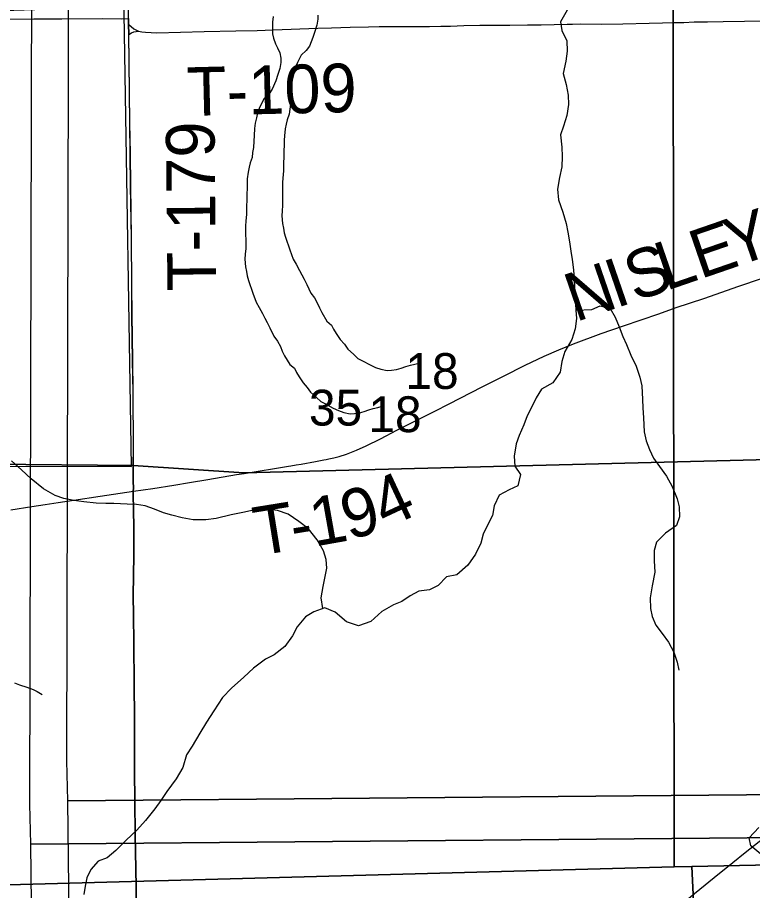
# Model space of a CAD drawing. Extents: x -21.1 to 50.3, y -4.9 to 22.1.
# Drawn here: x 2.72 to 3.578, y 15.856 to 16.876 of the extents above; entities that cross this region are included whole.
import ezdxf

# ---------------------------------------------------------------- set-up
doc = ezdxf.new("R2010")
doc.units = 0
for name, color, linetype in [('GM_X_Corporation', 7, 'Continuous'), ('GM_X_County_Road', 7, 'Continuous'), ('GM_X_Minor_River', 7, 'Continuous'), ('GM_X_Rail_Line_Text', 7, 'Continuous'), ('GM_X_Section', 7, 'Continuous'), ('GM_X_Section_Text', 7, 'Continuous'), ('GM_X_State_Route', 7, 'Continuous'), ('GM_X_Township_Road', 7, 'Continuous'), ('GM_X_Township_Road_Text', 7, 'Continuous'), ('SH_Cut_Line', 7, 'Continuous')]:
    doc.layers.add(name, color=color, linetype=linetype)

msp = doc.modelspace()

# ---------------------------------------------------------------- linework, layer by layer
at = {"layer": 'GM_X_Corporation'}
msp.add_lwpolyline([(2.1, 17.3693), (2.1, 16.3531), (2.8527, 16.3513), (2.8363, 17.363), (2.8365, 17.3865)], close=True, dxfattribs=at)
at = {"layer": 'GM_X_County_Road'}
for p, q in [((2.8491, 16.8748), (2.8493, 16.8682)), ((2.8493, 16.8682), (2.8496, 16.8562))]:
    msp.add_line(p, q, dxfattribs=at)
for points in [[(2.3484, 16.8666), (2.3505, 16.8667), (2.4002, 16.8675), (2.4654, 16.8688), (2.5213, 16.8703), (2.5555, 16.8712), (2.5834, 16.872), (2.6299, 16.8728), (2.6579, 16.8733), (2.6827, 16.8738), (2.7076, 16.8743), (2.7386, 16.8746), (2.7714, 16.8746), (2.8194, 16.8748), (2.8411, 16.8746), (2.8491, 16.8748)], [(2.8493, 16.8682), (2.85, 16.8675), (2.8525, 16.8654), (2.8554, 16.863), (2.858, 16.8615), (2.8601, 16.8606), (2.8608, 16.8603)], [(2.8608, 16.8603), (2.8647, 16.8593), (2.869, 16.8588), (2.8823, 16.8583), (2.9377, 16.8596), (2.9748, 16.8605), (2.9997, 16.861), (3.0182, 16.8615), (3.0705, 16.8635), (3.0863, 16.864), (3.1081, 16.8648), (3.1298, 16.8653), (3.1422, 16.8655), (3.1698, 16.8656), (3.1884, 16.8657), (3.201, 16.8657), (3.2144, 16.8659), (3.2257, 16.866), (3.2412, 16.8667), (3.2597, 16.8671), (3.2785, 16.867), (3.2949, 16.8671), (3.3156, 16.8674), (3.3314, 16.8674), (3.3619, 16.8682), (3.368, 16.8682), (3.3775, 16.8685), (3.402, 16.8684), (3.4268, 16.8687), (3.4577, 16.8693), (3.4731, 16.8698), (3.4854, 16.8701), (3.498, 16.8703), (3.5103, 16.8709), (3.5257, 16.8711), (3.5443, 16.8714), (3.5692, 16.8717), (3.594, 16.8722)], [(2.8496, 16.8562), (2.8529, 16.8581), (2.8556, 16.8593), (2.8608, 16.8603)], [(2.8551, 16.3226), (2.8776, 16.3259), (2.9021, 16.3297), (2.9205, 16.3328), (2.9419, 16.3364), (2.9756, 16.342), (2.9843, 16.3434)], [(2.7117, 16.301), (2.7363, 16.3048), (2.7517, 16.307), (2.767, 16.3094), (2.7854, 16.3121), (2.8162, 16.3167), (2.8551, 16.3226)]]:
    msp.add_lwpolyline(points, dxfattribs=at)
at = {"layer": 'GM_X_Minor_River'}
for points in [[(3.3619, 16.8848), (3.3542, 16.8712), (3.3557, 16.8609), (3.3613, 16.8487), (3.362, 16.8366), (3.3604, 16.8252), (3.3573, 16.8105), (3.3606, 16.7979), (3.3632, 16.7854), (3.3635, 16.7744), (3.3615, 16.7615), (3.3576, 16.749), (3.3541, 16.7388), (3.3556, 16.7247), (3.3562, 16.7137), (3.3558, 16.7016), (3.3527, 16.6891), (3.3507, 16.6754), (3.3517, 16.6629), (3.3566, 16.6488), (3.3607, 16.6355), (3.3625, 16.6253), (3.3647, 16.6139), (3.3661, 16.6032), (3.3676, 16.5934), (3.3694, 16.5812), (3.3701, 16.5691), (3.3708, 16.5554), (3.3721, 16.5342), (3.3728, 16.5243), (3.3712, 16.5122), (3.3674, 16.5), (3.3593, 16.486), (3.3558, 16.4743), (3.3535, 16.4618), (3.345, 16.4493), (3.3317, 16.4418), (3.3256, 16.4316), (3.3206, 16.421), (3.3152, 16.4108), (3.3113, 16.4002), (3.3059, 16.3877), (3.3024, 16.3779), (3.3001, 16.3635), (3.3007, 16.3517), (3.3075, 16.3422), (3.3044, 16.3289), (3.2941, 16.3241), (3.2823, 16.3181), (3.2765, 16.3056), (3.2746, 16.2942), (3.2696, 16.2844), (3.2638, 16.2723), (3.2611, 16.262), (3.2549, 16.2492), (3.2457, 16.236), (3.2331, 16.225), (3.221, 16.2225), (3.211, 16.2126), (3.2011, 16.2074), (3.1886, 16.206), (3.1783, 16.2003), (3.1688, 16.1939), (3.1589, 16.1898), (3.1452, 16.1819), (3.1326, 16.1703), (3.1181, 16.1654), (3.1041, 16.1701), (3.0909, 16.1811), (3.0788, 16.1865), (3.0659, 16.1817), (3.056, 16.176), (3.0464, 16.164), (3.041, 16.1537)], [(3.0185, 16.8774), (3.0174, 16.8706), (3.0175, 16.8569), (3.0187, 16.8519), (3.021, 16.8455), (3.0233, 16.8406), (3.026, 16.8349), (3.0272, 16.8284), (3.0273, 16.8235), (3.0262, 16.8166), (3.0236, 16.8094), (3.0214, 16.8021), (3.0173, 16.7922), (3.0135, 16.7869), (3.0079, 16.7815), (3.0034, 16.7731), (3.0004, 16.7662), (2.9989, 16.759), (2.9971, 16.7525), (2.9964, 16.7464), (2.9961, 16.7381), (2.9957, 16.7316), (2.9954, 16.724), (2.9943, 16.7183), (2.9936, 16.7126), (2.9914, 16.7061), (2.9903, 16.7011), (2.9892, 16.6954), (2.9881, 16.6874), (2.9878, 16.6821), (2.9878, 16.676), (2.9875, 16.6703), (2.9876, 16.6627), (2.9873, 16.6555), (2.987, 16.6463), (2.9863, 16.638), (2.9859, 16.6326), (2.9862, 16.606), (2.9854, 16.5995), (2.9851, 16.5938), (2.986, 16.5847), (2.9871, 16.5794), (2.9879, 16.5741), (2.9895, 16.5688), (2.9946, 16.554), (2.9985, 16.5434), (3.0019, 16.5373), (3.0058, 16.5301), (3.0085, 16.5248), (3.0112, 16.5199), (3.0143, 16.5135), (3.019, 16.5036), (3.0232, 16.4979), (3.0267, 16.4915), (3.029, 16.4862), (3.0317, 16.4809), (3.0379, 16.4707), (3.0432, 16.4662), (3.0456, 16.4612), (3.0486, 16.4563), (3.0533, 16.4491), (3.0582, 16.4439), (3.0621, 16.4382), (3.069, 16.4322), (3.074, 16.4273), (3.0793, 16.4246), (3.0885, 16.4198), (3.0946, 16.4168), (3.1007, 16.4145), (3.1083, 16.4131), (3.1133, 16.4135), (3.1193, 16.4143), (3.1246, 16.4159), (3.13, 16.4178), (3.1353, 16.4194), (3.1406, 16.4206), (3.1455, 16.4218)], [(3.0705, 16.8789), (3.0706, 16.874), (3.0695, 16.8671), (3.0669, 16.8599), (3.0647, 16.8527), (3.0606, 16.8427), (3.0568, 16.8374), (3.0512, 16.832), (3.0467, 16.8236), (3.0437, 16.8167), (3.0422, 16.8095), (3.0404, 16.803), (3.0397, 16.7969), (3.0394, 16.7886), (3.039, 16.7821), (3.0387, 16.7745), (3.0376, 16.7688), (3.0369, 16.7631), (3.0347, 16.7566), (3.0336, 16.7516), (3.0325, 16.7459), (3.0314, 16.7379), (3.0311, 16.7326), (3.0311, 16.7265), (3.0308, 16.7208), (3.0309, 16.7132), (3.0305, 16.706), (3.0302, 16.6968), (3.0296, 16.6885), (3.0292, 16.6832), (3.0294, 16.6565), (3.0287, 16.6501), (3.0284, 16.6444), (3.0292, 16.6352), (3.0304, 16.6299), (3.0312, 16.6246), (3.0328, 16.6193), (3.0379, 16.6045), (3.0418, 16.5939), (3.0452, 16.5878), (3.0491, 16.5806), (3.0518, 16.5753), (3.0545, 16.5704), (3.0576, 16.564), (3.0622, 16.5541), (3.0665, 16.5485), (3.07, 16.542), (3.0723, 16.5367), (3.075, 16.5314), (3.0812, 16.5212), (3.0865, 16.5167), (3.0888, 16.5118), (3.0919, 16.5068), (3.0966, 16.4997), (3.1015, 16.4944), (3.1054, 16.4887), (3.1123, 16.4827), (3.1173, 16.4778), (3.1226, 16.4751), (3.1318, 16.4703), (3.1379, 16.4673), (3.144, 16.4651), (3.1516, 16.4636), (3.1565, 16.464), (3.1626, 16.4648), (3.1679, 16.4664), (3.1732, 16.4683), (3.1786, 16.4699), (3.1839, 16.4711), (3.1888, 16.4723)], [(3.3722, 16.534), (3.3907, 16.5348), (3.4003, 16.5393), (3.412, 16.5362), (3.418, 16.5259), (3.4225, 16.5145), (3.427, 16.5035), (3.4311, 16.494), (3.4363, 16.4814), (3.4423, 16.4688), (3.4468, 16.4559), (3.449, 16.4457), (3.45, 16.4297), (3.4503, 16.4202), (3.451, 16.4085), (3.452, 16.3921), (3.4542, 16.3815), (3.458, 16.3712), (3.4628, 16.3613), (3.4696, 16.3514), (3.4779, 16.34), (3.4846, 16.3282), (3.4902, 16.3138), (3.4928, 16.3043), (3.4931, 16.2925), (3.4896, 16.2826), (3.4767, 16.2736), (3.4664, 16.2631), (3.4636, 16.2532), (3.4636, 16.2411), (3.4642, 16.2282), (3.4611, 16.2119), (3.4587, 16.1982), (3.4594, 16.1857), (3.4612, 16.1762), (3.4654, 16.1659), (3.4729, 16.1564), (3.4804, 16.1461), (3.4864, 16.1347), (3.4905, 16.1229), (3.4923, 16.1134)], [(3.0765, 16.1857), (3.0743, 16.1979), (3.0767, 16.2112), (3.0787, 16.221), (3.081, 16.2328), (3.0803, 16.243), (3.077, 16.2529), (3.0698, 16.2659), (3.0597, 16.2785), (3.0484, 16.2873), (3.0359, 16.2957), (3.0234, 16.2999), (3.0086, 16.3019), (2.9953, 16.3005), (2.9828, 16.2979), (2.9691, 16.2949), (2.9516, 16.2909), (2.9395, 16.2891), (2.9247, 16.2891), (2.9118, 16.2915), (2.9, 16.2946), (2.8902, 16.2973), (2.8796, 16.3016), (2.8686, 16.3054), (2.8588, 16.307), (2.8478, 16.3075), (2.8322, 16.3083), (2.8227, 16.3084), (2.8113, 16.3088), (2.7969, 16.31), (2.7852, 16.3116), (2.7738, 16.314), (2.7636, 16.3175), (2.75, 16.3255), (2.7356, 16.337), (2.7243, 16.3477), (2.7126, 16.358)], [(3.041, 16.1537), (3.0318, 16.1413), (3.0196, 16.1315), (3.0094, 16.1262), (2.9952, 16.1157), (2.9842, 16.1055), (2.9697, 16.0923), (2.959, 16.0814), (2.949, 16.0659), (2.9406, 16.0527), (2.9325, 16.0398), (2.9237, 16.0247), (2.9172, 16.0145), (2.9129, 15.9997), (2.9048, 15.9865), (2.8941, 15.9718), (2.8872, 15.9612), (2.8799, 15.9514), (2.8692, 15.9378), (2.8589, 15.9265), (2.8467, 15.9148), (2.8345, 15.9027), (2.8242, 15.8944), (2.8139, 15.8903), (2.8051, 15.8805), (2.8005, 15.8707), (2.7985, 15.8612), (2.7969, 15.8513)], [(2.7159, 16.0988), (2.722, 16.0962), (2.7304, 16.0936), (2.7377, 16.091), (2.7426, 16.0884), (2.7483, 16.085)], [(3.588, 15.8986), (3.5764, 15.9083), (3.5746, 15.9178), (3.5859, 15.9298)]]:
    msp.add_lwpolyline(points, dxfattribs=at)
at = {"layer": 'GM_X_Rail_Line_Text'}
for points in [[(2.8489, 16.8892), (2.8489, 16.8754), (2.8491, 16.8687), (2.8494, 16.8567), (2.8498, 16.8245), (2.8506, 16.7532), (2.8511, 16.7173), (2.8516, 16.6794), (2.8524, 16.6191), (2.8528, 16.563), (2.8531, 16.5288), (2.8538, 16.4761), (2.8544, 16.4387), (2.8548, 16.3733), (2.8547, 16.3527), (2.9841, 16.3439), (3.8594, 16.3662)], [(3.8594, 16.3662), (2.9841, 16.3439), (2.8547, 16.3527), (2.8548, 16.3349), (2.855, 16.3256), (2.8549, 16.3231), (2.8548, 16.3167), (2.8552, 16.303), (2.8554, 16.278), (2.8554, 16.2486), (2.8551, 16.2233), (2.8549, 16.2016), (2.8552, 16.1768), (2.8554, 16.1457), (2.8559, 16.096), (2.8561, 16.0588), (2.8563, 16.0308), (2.8564, 16.006), (2.8567, 15.9502), (2.857, 15.9316), (2.8572, 15.9223), (2.8581, 15.8603), (2.8583, 15.8417)], [(2.8583, 15.8417), (2.8581, 15.8603), (2.8572, 15.9223), (2.857, 15.9316), (2.8567, 15.9502), (2.8564, 16.006), (2.8563, 16.0308), (2.8561, 16.0588), (2.8559, 16.096), (2.8554, 16.1457), (2.8552, 16.1768), (2.8549, 16.2016), (2.8551, 16.2233), (2.8554, 16.2486), (2.8554, 16.278), (2.8552, 16.303), (2.8548, 16.3167), (2.8549, 16.3231), (2.855, 16.3256), (2.8548, 16.3349), (2.8547, 16.3527), (2.3532, 16.3572), (2.1, 16.3492), (2.1, 14.1)]]:
    msp.add_lwpolyline(points, dxfattribs=at)
at = {"layer": 'GM_X_Section'}
for points in [[(3.8217, 16.9904), (3.8359, 15.9702), (2.7784, 15.9607), (2.7773, 16.0074), (2.7797, 16.9773)], [(3.7784, 16.9399), (3.7926, 15.9197), (2.7351, 15.9102), (2.734, 15.9568), (2.7365, 16.9268)], [(3.4856, 16.8942), (3.4867, 15.8836), (2.5208, 15.8578), (2.478, 15.8578), (2.4791, 16.8774), (2.9755, 16.8927)], [(4.4944, 16.9022), (4.4951, 15.9048), (3.5076, 15.884), (3.4867, 15.8836), (3.4856, 16.8942)], [(3.8359, 15.9702), (3.8488, 14.9511), (2.7899, 14.9492), (2.7784, 15.9607)], [(3.7926, 15.9197), (3.8056, 14.9006), (2.7466, 14.8987), (2.7351, 15.9102)], [(4.4951, 15.9048), (4.5163, 14.8604), (3.5576, 14.829), (3.5076, 15.884)], [(3.5076, 15.884), (3.5576, 14.829), (2.5595, 14.8074), (2.5208, 15.8578), (3.4867, 15.8836)]]:
    msp.add_lwpolyline(points, close=True, dxfattribs=at)
at = {"layer": 'GM_X_State_Route'}
msp.add_lwpolyline([(3.5001, 15.8439), (3.5338, 15.8712), (3.5555, 15.8887), (3.5699, 15.9003), (3.5917, 15.9177)], dxfattribs=at)
at = {"layer": 'GM_X_Township_Road'}
for p, q in [((2.8493, 16.8682), (2.8491, 16.8748)), ((2.8496, 16.8562), (2.8493, 16.8682))]:
    msp.add_line(p, q, dxfattribs=at)
for points in [[(2.8491, 16.8748), (2.8491, 16.8887), (2.8487, 16.8997), (2.8481, 16.924), (2.8474, 16.9599), (2.847, 16.9778), (2.8467, 16.9971), (2.8458, 17.0416), (2.8453, 17.0653), (2.8443, 17.1053), (2.8435, 17.1394), (2.8431, 17.1552), (2.8419, 17.2048), (2.8413, 17.2348), (2.8407, 17.2667), (2.8394, 17.3254), (2.8384, 17.3761)], [(2.8549, 16.3521), (2.855, 16.3728), (2.8546, 16.4382), (2.8541, 16.4755), (2.8533, 16.5282), (2.853, 16.5625), (2.8526, 16.6185), (2.8518, 16.6789), (2.8513, 16.7168), (2.8508, 16.7526), (2.85, 16.8239), (2.8496, 16.8562)], [(2.9843, 16.3434), (3.0364, 16.3519), (3.0391, 16.3524), (3.0452, 16.3533), (3.0512, 16.3543), (3.0677, 16.3573), (3.0775, 16.3591), (3.0804, 16.3598), (3.0833, 16.3604), (3.0893, 16.3616), (3.0953, 16.3631), (3.1041, 16.3659), (3.1156, 16.3705), (3.1269, 16.3755), (3.1436, 16.3839), (3.163, 16.3938), (3.1879, 16.4065), (3.2073, 16.4163), (3.2239, 16.4248), (3.2626, 16.4444), (3.2876, 16.4571), (3.3126, 16.4697), (3.335, 16.4803), (3.3521, 16.4879), (3.3694, 16.4949), (3.4014, 16.5067), (3.4278, 16.5159), (3.4688, 16.53), (3.4893, 16.5371), (3.5217, 16.5477), (3.5626, 16.5622), (3.5891, 16.5713)], [(2.8551, 16.3226), (2.8552, 16.325), (2.855, 16.3343), (2.8549, 16.3521)], [(2.8585, 15.8412), (2.8583, 15.8598), (2.8574, 15.9218), (2.8572, 15.9311), (2.8569, 15.9497), (2.8566, 16.0055), (2.8565, 16.0303), (2.8563, 16.0582), (2.8561, 16.0955), (2.8557, 16.1452), (2.8554, 16.1762), (2.8551, 16.2011), (2.8554, 16.2228), (2.8556, 16.2481), (2.8556, 16.2774), (2.8554, 16.3025), (2.855, 16.3161), (2.8551, 16.3226)]]:
    msp.add_lwpolyline(points, dxfattribs=at)
at = {"layer": 'SH_Cut_Line'}
for points in [[(8.9, 20.9), (2.1, 20.9), (2.1, 16.3492), (2.3532, 16.3572), (2.8547, 16.3527), (2.9841, 16.3439), (3.8594, 16.3662)], [(3.8594, 16.3662), (2.9841, 16.3439), (2.8547, 16.3527), (2.3532, 16.3572), (2.1, 16.3492), (2.1, 14.1), (8.9, 14.1)]]:
    msp.add_lwpolyline(points, dxfattribs=at)

# ---------------------------------------------------------------- texts
at = {"layer": 'GM_X_Section_Text'}
for s, p in [('18', (3.1728, 16.4421)), ('35', (3.0601, 16.3993)), ('18', (3.1295, 16.3916))]:
    msp.add_text(s, height=0.04186, rotation=0, dxfattribs=at).set_placement(p)
at = {"layer": 'GM_X_Township_Road_Text'}
for s, height, rotation, p in [('T-109', 0.05682, 1.4048, (2.9181, 16.761)), ('T-179', 0.05682, 90.557, (2.9516, 16.5564)), ('Y', 0.0568, 18.9677, (3.5575, 16.5841)), ('E', 0.0568, 19.034, (3.5174, 16.5702)), ('S', 0.0568, 19.0391, (3.4409, 16.5438)), ('L', 0.0568, 19.038, (3.4772, 16.5564)), ('N', 0.0568, 19.038, (3.3716, 16.5199)), ('I', 0.0568, 19.0348, (3.4189, 16.5362)), ('4', 0.0568, 25.0312, (3.15, 16.2782)), ('9', 0.0568, 15.578, (3.1067, 16.2653)), ('1', 0.0568, 10.084, (3.0664, 16.2578)), ('T', 0.0568, 9.1587, (3.0004, 16.2471)), ('-', 0.0568, 9.328, (3.0426, 16.2539))]:
    msp.add_text(s, height=height, rotation=rotation, dxfattribs=at).set_placement(p)

doc.saveas('drawing.dxf')
